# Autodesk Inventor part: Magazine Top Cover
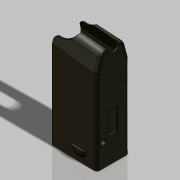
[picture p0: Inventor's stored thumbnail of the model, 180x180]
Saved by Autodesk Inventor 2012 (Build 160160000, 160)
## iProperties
Category: Sten MK II Magazine
Company: MH Vaaben Teknik
Created: 2011-12
Part Number: Magazine Top Cover
Material: Steel, Mild
Document SubType Name: Modeling
Designer: Michael Høgh
Density: 7.86 g/cm^3
Project: Sten MK II
Engineer: MH Vaaben Teknik
Mass: 49.0053 g
Surface Area: 128.392 cm^2
Volume: 6.23478 cm^3
Author: Michael Høgh
Title: Magazine Top Cover
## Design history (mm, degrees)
sketch "Sketch1"
  geometry: L1 (19, 11.75)-(19, -11.75); L2 (-19, -7.633)-(-19, 7.633); L3 (-21.817, 0.006)-(19.671, 0.006); L4 (19, 11.75)-(-15.884, 10.832); L5 (19, -11.75)-(-15.884, -10.832); A1 r 3.2 centre (-15.8, 7.633) between (-15.884, 10.832) and (-19, 7.633); A2 r 3.2 centre (-15.8, -7.633) between (-19, -7.633) and (-15.884, -10.832); 2 further points
  constraints: 10 end point, 4 point on circle, 4 tangent, 2 centre point, 1 horizontal alignment, 1 midpoint, 1 parallel, 1 perpendicular
  dimensions: "d0" = 23.5 distance of L1.start L1.end; "d2" = 1.5074 deg angle of L4 L3; "d3" = 1.5074 deg angle of L5 L3; "d4" = 6.4 diameter of A1; "d5" = 6.4 diameter of A2; "d6" = 38 distance between parallel lines of L1 L2
extrude "Extrusion1" new body sketch "Sketch1" distance "d7" = 75.7; taper "d8" = 0 deg
sketch "Sketch2"
  geometry: L1 (-75.7, 23.5)-(-75.7, 0) reference; L2 (0, 0)-(-75.7, 0) reference; L3 (0, 23.5)-(-75.7, 23.5) reference; L4 (-61.2, 23.5)-(-75.7, 19.615); L5 (-75.7, 3.885)-(-61.2, 0); L6 (-75.7, 23.5)-(-61.2, 23.5); L7 (-75.7, 0)-(-61.2, 0); L8 (-75.7, 0)-(-75.7, 3.885); L9 (-75.7, 19.615)-(-75.7, 23.5); 1 further point
  constraints: 12 end point, 2 collinear, 1 point on line
  dimensions: "d11" = 14.5 distance of L4.start L1.start; "d12" = 14.5 distance of L5.end L1.end; "d13" = 15 deg angle of L3 L4; "d14" = 15 deg angle of L5 L2
extrude "Extrusion2" cut sketch "Sketch2" stored distance "d15" = 75.7; taper "d16" = 0 deg
workplane "Work Plane Left"
workplane "Work Plane Right"
sketch "Sketch11"
  geometry: L1 (0, 0)-(61.2, 0) reference; L2 (0, 0)-(0, -34.884) reference; L3 (9, -7.5)-(9, -19); A1 r 5.75 centre (9, -13.25) between (9, -7.5) and (9, -19); 2 further points
  constraints: 2 end point, 2 point on circle, 1 centre point, 1 parallel
  dimensions: "d61" = 7.5 distance from line of L3.start L1
extrude "Extrusion7" join sketch "Sketch11" distance "d64" = 1; taper "d65" = 0 deg; dims "d67" = 0.5, "d68" = 0
fillet "Fillet2" dims "d66" = 5.7
sketch "Sketch12"
  geometry: L1 (9, 19)-(9, 7.5); L2 (0, 0)-(61.2, 0) reference; L3 (0, 34.884)-(0, 0) reference; A1 r 5.75 centre (9, 13.25) between (9, 19) and (9, 7.5); 1 further point
  constraints: 2 end point, 2 point on circle, 1 centre point, 1 midpoint, 1 vertical
  dimensions: "d69" = 11.5 distance of L1.start L1.end; "d70" = 7.5 distance from line of L1.end L2; "d71" = 9 distance between parallel lines of L1 L3
extrude "Extrusion8" join sketch "Sketch12" distance "d72" = 1; taper "d74" = 0 deg; dims "d73" = 0.7, "d75" = 0
fillet "Fillet3" dims "d76" = 5.7
sketch "Sketch20"
  geometry: L1 (75.7, 18.5)-(75.7, 0); L2 (75.7, 0)-(74.2, 0); L3 (75.7, 18.5)-(74.2, 0); L4 (61.136, 0)-(73.7, 0) reference; L5 (75.7, 37.992)-(75.7, 0) reference; 3 further points
  constraints: 6 end point, 1 perpendicular
  dimensions: "d119" = 0 distance between parallel lines of L2 L4; "d120" = 1.5 distance of L1.end L2.end; "d121" = 18.5 distance of L1.end L1.start; "d132" = 0 distance between parallel lines of L1 L5
extrude "Extrusion21" cut sketch "Sketch20" stored distance "d133" = 10; taper "d134" = 0 deg
fillet "Fillet9" dims "d135" = 5.25
fillet "Fillet10" dims "d136" = 2
shell "Shell11" dims "d143" = 1
sketch "Sketch18"
  geometry: C1 r 4.4 at (-74.2, 11.75); 1 further point
  constraints: 1 centre point
  dimensions: "d111" = 8.8 diameter of C1; "d112" = 74.2 distance of C1.centre point (0, 11.75)
extrude "Extrusion23" cut sketch "Sketch18" stored distance "d144" = 10; taper "d145" = 0 deg
sketch "Sketch22"
  geometry: L1 (69.7, 41.989)-(69.7, 29.289); L2 (75.7, 38)-(75.7, 18.611) reference; L3 (72.356, 0)-(69.936, 0) reference; L4 (82.4, 41.989)-(69.7, 41.989); L5 (68.54, 41.989)-(69.748, 28.182); L6 (68.545, 41.941)-(93.548, 41.941); L7 (69.7, 41.989)-(68.54, 41.989); A1 r 12.7 centre (82.4, 29.289) between (82.4, 41.989) and (69.7, 29.289); 1 further point
  constraints: 10 end point, 3 point on circle, 3 tangent, 1 centre point, 1 horizontal, 1 parallel, 1 perpendicular, 1 point on line, 1 vertical
  dimensions: "d146" = 25.4 diameter of A1; "d147" = 6 distance between parallel lines of L1 L2; "d148" = 29.289 distance from line of L3 A1.centre; "d175" = 85 deg angle of L5 L6
extrude "Extrusion24" cut sketch "Sketch22" stored distance "d149" = 0; taper "d150" = 0 deg
sketch "Sketch23"
  geometry: L1 (0, 0)-(0, 19.393) reference; L2 (-34, 6.447)-(-18.5, 6.447); L3 (-18.5, 6.447)-(-18.5, 12.947); L4 (-18.5, 12.947)-(-34, 12.947); L5 (-34, 12.947)-(-34, 6.447); L6 (0, 21.393)-(-61.402, 21.393) reference; L7 (-61.402, -1.999)-(0, -1.999) reference; 2 further points
  constraints: 8 end point, 2 parallel, 1 horizontal, 1 perpendicular
  dimensions: "d153" = 6.5 distance of L4.end L2.start; "d155" = 18.5 distance between parallel lines of L3 L1; "d156" = 34 distance between parallel lines of L5 L1; "d157" = 8.446 distance between parallel lines of L6 L4
extrude "Extrusion26" cut sketch "Sketch23" stored distance "d159" = 10; taper "d160" = 0 deg
sketch "Sketch24"
  geometry: L1 (29.192, 10.426)-(38.932, 10.426); L2 (38.932, 10.426)-(38.932, 19.126); L3 (38.932, 19.126)-(29.192, 19.126); L4 (34.842, 3.49)-(34.842, 64.626) reference; A1 r 4.35 centre (29.192, 14.776) between (29.192, 10.426) and (29.192, 19.126); 4 further points; 1 other entity
  constraints: 6 end point, 2 point on circle, 2 tangent, 1 centre point, 1 horizontal, 1 perpendicular, 1 other
  dimensions: "d161" = 8.7 diameter of A1; "d162" = 5.65 distance from line of A1.centre L4; "d163" = 45.5 distance from line of L3 L4.end; "d164" = 54.2 distance from line of L1 L4.end
extrude "Extrusion27" cut sketch "Sketch24" distance "d165" = 1; taper "d166" = 0 deg
sketch "Sketch25"
  geometry: L1 (54.2, -2.053)-(54.2, -5.702) reference; L2 (45.5, -0.295)-(45.5, -2.053) reference; L3 (54.2, -2.704)-(45.5, -2.704); L4 (45.5, -2.704)-(45.5, -1); L5 (45.5, -1)-(54.2, -1); L6 (54.2, -1)-(54.2, -2.704); L7 (61.136, 0)-(0, 0) reference; 1 further point
  constraints: 8 end point, 2 parallel, 2 point on line, 1 horizontal, 1 perpendicular
  dimensions: "d167" = 1 distance between parallel lines of L5 L7
extrude "Extrusion28" cut sketch "Sketch25" distance "d168" = 2; taper "d169" = 0 deg
sketch "Sketch27"
  geometry: L1 (71.147, 44.325)-(-3.066, 44.325); L2 (-3.066, 44.325)-(-3.066, 33.5); L3 (-3.066, 33.5)-(71.147, 33.5); L4 (71.147, 33.5)-(71.147, 44.325); L5 (0, 38)-(69.7, 38) reference; 1 further point
  constraints: 8 end point, 2 parallel, 1 horizontal, 1 perpendicular
  dimensions: "d170" = 4.5 distance between parallel lines of L5 L3
extrude "Extrusion29" cut sketch "Sketch27" stored distance "d171" = 2; taper "d172" = 0 deg
fillet "Fillet12" dims "d174" = 3.6
chamfer "Chamfer1" distance "d176" = 0.1; stored, may be unused: second distance "d177" = 2, angle "d178" = 45 deg
chamfer "Chamfer2" distance "d179" = 0.1; stored, may be unused: second distance "d180" = 2, angle "d181" = 45 deg
chamfer "Chamfer3" distance "d182" = 0.1; stored, may be unused: second distance "d183" = 2, angle "d184" = 45 deg
chamfer "Chamfer4" distance "d185" = 0.1; stored, may be unused: second distance "d186" = 2, angle "d187" = 45 deg
chamfer "Chamfer5" distance "d188" = 0.1; stored, may be unused: second distance "d189" = 2, angle "d190" = 45 deg
sketch "Sketch28"
  geometry: L1 (-34, 6.347)-(-18.3, 6.347) reference; L2 (-54.2, 20.439)-(-54.2, 21.393) reference; C1 r 2 at (-16.2, 3.197); 2 further points
  constraints: 1 centre point
  dimensions: "d191" = 4 diameter of C1; "d193" = 3.15 distance from line of C1.centre L1; "d194" = 38 distance from line of C1.centre L2
extrude "Extrusion30" cut sketch "Sketch28" stored distance "d195" = 10; taper "d196" = 0 deg
chamfer "Chamfer6" distance "d197" = 0.1; stored, may be unused: second distance "d198" = 2, angle "d199" = 45 deg
body "Solid1"
other parameters: "d28" = 0.26309, "d59" = -0.26309
